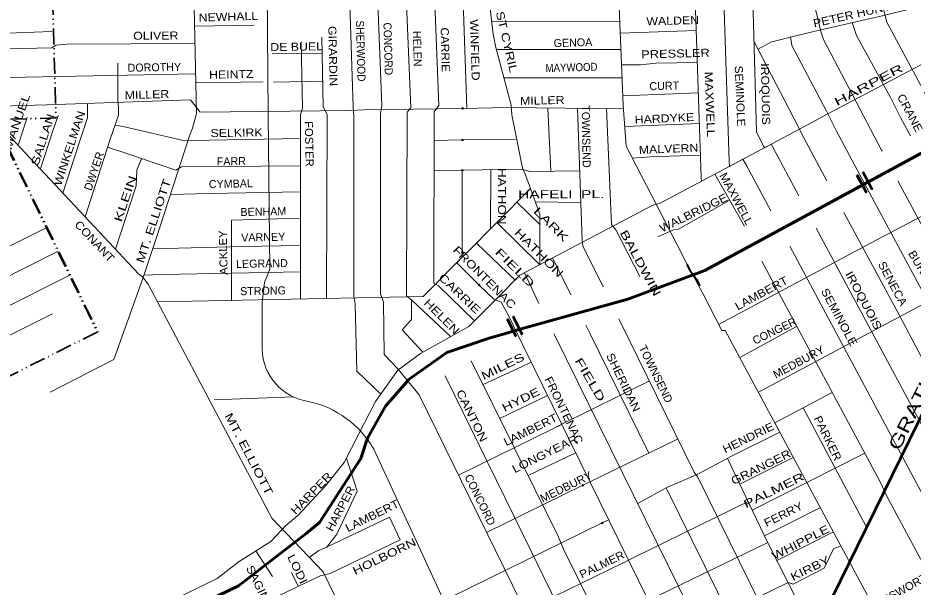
# Model space of a CAD drawing. Extents: x 34705 to 138605, y 34275 to 143551.
# Drawn here: x 100858 to 109243, y 116985 to 122315 of the extents above; entities that cross this region are included whole.
import ezdxf
from ezdxf.enums import TextEntityAlignment as Align

# ---------------------------------------------------------------- set-up
doc = ezdxf.new("R2010")
doc.units = 0
doc.header["$LTSCALE"] = 30
doc.header["$PDMODE"] = 32
doc.header["$PDSIZE"] = 15
doc.linetypes.add('DASH_DOUBLE_DOT', pattern=[9.2, 5, -1.2, 0.3, -1.2, 0.3, -1.2])
for name, color, linetype, lineweight in [('1', 7, 'Continuous', 13), ('11', 7, 'Continuous', 13), ('50', 7, 'Continuous', 13), ('51', 7, 'Continuous', 35), ('59', 7, 'DASH_DOUBLE_DOT', 106)]:
    doc.layers.add(name, color=color, linetype=linetype, lineweight=lineweight)

msp = doc.modelspace()

# ---------------------------------------------------------------- linework, layer by layer
at = {"layer": '1'}
for p, q in [((105027.35, 122464.2), (105063.96, 121468.67)), ((102512.54, 122236.39), (103070.94, 122246.19)), ((105294.72, 122280.67), (106495.17, 122285.71)), ((106499.93, 122172.34), (107210.12, 122197.35)), ((105340.36, 122019.42), (106506.34, 122019.42)), ((103238.5, 121979.98), (103706.88, 121985.02)), ((105409.65, 121754.77), (106517.44, 121754.77)), ((103252.36, 121712.48), (103706.84, 121723.05)), ((106524.58, 121584.56), (107230.94, 121612.16)), ((105014, 121467.85), (105023.8, 121468)), ((105822.22, 121470.77), (105848.2, 120879.51)), ((106541.46, 121299.33), (107241.08, 121327.1)), ((104758.49, 121167.98), (105022.74, 121171.66)), ((105012.19, 121171.48), (105022.74, 121171.63)), ((105022.74, 121171.66), (105519.48, 121178.56)), ((104758.49, 120882.52), (105021.73, 120887.65)), ((105010.45, 120887.4), (105021.73, 120887.62)), ((105018.37, 120887.58), (105019.63, 120301.09)), ((105040.81, 120093.95), (105656.91, 120715.02)), ((105532.32, 120589.42), (105746.37, 120381.6)), ((105704.29, 120592.05), (106130.6, 120586.37)), ((102857.88, 120422.51), (103505.39, 120438.98)), ((102857.88, 120422.51), (102857.88, 119665.83)), ((105019.63, 120300.97), (105020.02, 120120.9)), ((99269.42, 119146.46), (101236.59, 120130.37)), ((105020.02, 120120.9), (105020.02, 120120.24)), ((105036.1, 120089.2), (105040.81, 120093.95)), ((105037.02, 120089.09), (105041.27, 120093.37)), ((105866.33, 120066.75), (106037.13, 119721.74)), ((99381.26, 118924.05), (101345.14, 119906.31)), ((105178.65, 119813.82), (105178.65, 119813.82)), ((105277.58, 119622.72), (105349.19, 119694.35)), ((105277.58, 119622.72), (105349.19, 119694.35)), ((105081.79, 119426.86), (105277.58, 119622.72)), ((107620.36, 119133.63), (108152.17, 119425.93)), ((105414.65, 119357.96), (105506, 119383.57)), ((105574.6, 119048.98), (105652.63, 119085.34)), ((105652.63, 119085.34), (105665.78, 119091.46)), ((105214.89, 118881.39), (105574.6, 119048.98)), ((104859.72, 118963.6), (105661.1, 117328.25)), ((105938.82, 118503.26), (106773.19, 118915.08)), ((105372.16, 118563.86), (105735.52, 118738.13)), ((105735.52, 118738.13), (105806.59, 118772.21)), ((105806.59, 118772.21), (105819.7, 118778.5)), ((108213.12, 118664.44), (108807.71, 117545.53)), ((105873.75, 118471.14), (105938.82, 118503.26)), ((105874.69, 118471.09), (105939.03, 118502.84)), ((104985.66, 118032.79), (105873.75, 118471.14)), ((106203.69, 117964.56), (107035.52, 118371.06)), ((106010.22, 118207.51), (106070.33, 118235.8)), ((106070.33, 118235.8), (106083.54, 118242.02)), ((104037.05, 117884.95), (103936.85, 118193.13)), ((105635.95, 118031.32), (106010.22, 118207.51)), ((107618.46, 117949.89), (108120.95, 118198.39)), ((105248.33, 117497.69), (106149.66, 117938.16)), ((106149.66, 117938.16), (106203.69, 117964.56)), ((106150.62, 117938.12), (106203.89, 117964.15)), ((103846.46, 117479.75), (104037.05, 117884.95)), ((103743.35, 117354.46), (104338.18, 117640.06)), ((104338.18, 117640.06), (104439.72, 117429.24)), ((101946.58, 115440.18), (106331.92, 117586.09)), ((103235.24, 117630.67), (103716.27, 117128.42)), ((106331.92, 117586.09), (106378.55, 117608.91)), ((106331.92, 117586.09), (106378.55, 117608.91)), ((106378.55, 117608.91), (106391.74, 117615.36)), ((103748.97, 117357.16), (103846.46, 117479.75)), ((107965.92, 117235.45), (108496.16, 117503.7)), ((103243.79, 117083.32), (103087.16, 117325.11)), ((103587.67, 117262.7), (103677.32, 117328.13)), ((103677.32, 117328.13), (103743.35, 117354.46)), ((105661.1, 117328.25), (106793.71, 115026.96)), ((105968.83, 117341.08), (107047.11, 115150.16)), ((103420.21, 117122.89), (103484.63, 116992.87))]:
    msp.add_line(p, q, dxfattribs=at)
at = {"layer": '1', "lineweight": 53}
msp.add_lwpolyline([(101368.9, 103017.54), (102548.84, 105055.11), (103212.24, 106184.42), (103282.07, 106324.13), (104294.63, 108304.78), (105138.43, 110039.49), (106145.17, 112117.65), (109289.05, 118526.78), (110743.87, 121478.11), (113275.26, 126686.61), (116465.7, 133274.74), (120395.18, 141348.71), (121157.51, 142914.61), (121243.66, 143093.14)], dxfattribs=at)
at = {"layer": '1'}
for points in [[(105908.84, 142655.73), (106002.49, 139831.85), (106021.72, 138812.17), (106489.73, 122415.45), (106528.19, 121498.37), (106553.84, 121113.59), (107079.54, 120098.72), (107093.68, 120071.85)], [(102374.85, 126669.09), (102396.28, 126261.72), (102409.1, 126024.43), (102377.05, 125960.3), (102396.28, 125543.45), (102409.1, 125408.77), (102428.34, 125254.86), (102460.39, 124049.19), (102460.39, 123978.65), (102498.86, 122702.43), (102505.27, 122561.34), (102530.91, 121416.61), (102492.45, 121281.93), (102466.8, 121211.39), (102152.66, 120249.42), (102030.85, 119883.87), (101755.18, 119117.51), (101158.95, 118809.68)], [(106263.71, 125304.33), (106021.72, 125025.59), (105887.09, 124871.68), (105848.62, 124833.2), (105560.13, 124461.24), (105534.48, 124377.87), (105496.02, 124005.9), (105354.97, 123396.66), (105226.75, 122890.02), (105265.22, 122556.54), (105297.27, 122261.53), (105310.1, 122165.34), (105335.74, 122037.08), (105476.78, 121498.37), (105483.19, 121408.59), (105585.77, 120908.37), (105611.42, 120844.23), (105746.05, 120478.69), (105747.62, 120004.13)], [(108665.24, 124101.95), (108697.65, 123670.07), (108762.34, 123677.67), (108858.01, 122880.22), (108863.83, 122810.42), (108997.57, 122275.29), (109491.61, 121350.64)], [(103922.86, 124068.53), (103960.58, 122635.1), (103999.04, 121480.74), (104005.45, 121390.96), (104005.45, 120416.16), (104005.45, 119710.72), (104018.28, 119633.76), (104031.1, 119008.49), (104256.6, 118790.34)], [(104185.08, 124073.75), (104223.43, 122615.86), (104268.31, 121493.57), (104255.49, 121416.61), (104255.49, 119729.96), (104281.13, 119653), (104289.14, 119164.01), (104417.36, 119029.34), (104616.1, 118785.64), (106525.24, 114896.44)], [(104453.69, 124079.09), (104492.69, 122596.62), (104537.57, 121474.33), (104505.52, 121432.65), (104499.1, 119713.93), (104550.39, 119669.04), (104910.16, 119331.3)], [(104716.92, 124084.33), (104755.55, 122615.86), (104800.42, 121493.57), (104755.55, 121435.85), (104753.94, 119830.97), (104798.82, 119805.32), (105134.66, 119479.75)], [(108143.68, 124059.53), (108154.44, 123898.11), (108173.97, 123608.61), (108238.66, 123616.21), (108340.51, 122740.62), (108392.24, 122480.26), (108311.57, 122461.01), (108381.21, 122176.41), (108404.47, 122112.43), (108945.23, 121077.1), (108951.46, 121065.54)], [(107229.91, 123822.5), (107265.6, 122481.59), (107200.26, 122480.4), (107258.98, 120824.07), (107259.85, 120785.33), (107385.25, 120851.83), (107663.1, 120363.33)], [(107790.96, 122022.99), (107911.74, 122088.44), (108079.3, 122132.81), (108325.71, 122191.96), (108951.6, 122334.93), (109542.99, 122477.9), (109641.56, 122507.48), (110504.01, 122714.53), (111233.39, 122887.08), (111258.03, 122887.08), (111393.51, 122814.8)], [(99925.23, 122819.5), (100622.03, 121373.32), (100698.96, 121296.37), (101987.58, 119917.54), (102026.05, 119891.89), (102077.34, 119821.35), (103235.24, 117630.67)], [(107469.12, 122485.12), (107520.08, 120972.74), (107522.31, 120924.52), (107648.29, 120991.33), (107683.19, 120933.35), (107909.99, 120509.24)], [(107741.03, 122490.04), (107776.48, 121248.68), (107840.45, 121114.9), (107850.71, 121098.69), (107915.86, 121133.24), (107933.48, 121097.45), (108173.94, 120648.83)], [(108672.36, 122271.15), (108712.65, 122150.24), (109032.45, 121568.59), (109125.49, 121382.46), (109218.18, 121209.82)], [(100244.15, 122157.6), (100511.94, 122162.38), (101177.26, 122187.03)], [(103512.33, 122089.75), (103524.63, 121467.91), (103505.39, 121410.2), (103505.39, 119683.21)], [(103703.9, 122134.36), (103716.96, 121480.74), (103755.42, 121410.2), (103749.06, 119687.87)], [(107752.23, 122097.85), (108125.36, 121376.64), (108218.4, 121190.51), (108435.4, 120788.92)], [(108093.55, 122136.23), (108107.92, 122057.18), (108427.73, 121446.44), (108520.76, 121260.31), (108696.71, 120932.51)], [(100315.31, 122009.91), (100462.66, 122019.42), (101177.26, 122034.21), (101216.68, 122058.86), (101315.25, 122068.72), (102516.19, 122073.73)], [(105349.19, 119694.35), (105559.89, 119905.12), (106797.31, 120557.79), (106873.24, 120580.29), (108178.16, 121272.35), (108436.9, 121413.01), (109494.34, 121968.63)], [(101793.64, 121891.18), (101793.64, 121532.04), (101800.06, 121480.74), (101800.06, 121403.78), (101723.12, 121179.32), (101487.65, 120452.47)], [(106512.34, 121876.45), (106689.52, 121876.45), (106832.44, 121891.24), (107220.83, 121896.29)], [(100438.28, 121760.06), (100607.39, 121754.77), (102515.15, 121791.78)], [(102524.41, 121706.9), (103154.6, 121717.77), (103154.6, 121717.77)], [(100580.97, 121485.17), (101125.29, 121501.03), (101130.57, 121501.03), (102475.51, 121548.6), (102565.35, 121432.3), (103971.07, 121448.16), (104097.9, 121453.45), (105023.8, 121468.03)], [(101511.56, 121506.39), (101511.56, 121455.09), (101511.56, 121378.13), (101434.63, 121153.67), (101279.58, 120675.1)], [(105023.8, 121468.03), (105440.21, 121474.59), (106530.51, 121463.69)], [(106098.3, 121468.01), (106143.53, 120233.39), (106149.94, 120182.09), (106338.85, 119798.05)], [(106369.7, 121465.3), (106419.21, 120380.9), (106457.67, 120329.59), (106682.06, 119893.5)], [(100944.91, 121383.2), (100940.98, 121371.72), (100860.55, 121123.47)], [(101233.88, 121400.07), (101184.6, 121256.28), (101069.23, 120900.18)], [(101772.65, 121310.72), (101857.21, 121294.86), (102422.67, 121162.7), (102480.8, 121167.98), (103505.39, 121184.17)], [(101698.67, 121104.55), (101878.35, 121046.4), (102338.11, 120887.81), (102390.96, 120919.52), (103505.39, 120930.35)], [(102016.19, 120996.7), (101973.15, 120890.73), (101966.74, 120743.23), (101770.99, 120149.3)], [(106612.66, 121000.04), (106778.54, 121014.68), (107251.62, 121031)], [(107421.41, 119444.69), (108231.39, 119878.74), (108784.22, 120175.62), (110081.92, 120856.7), (110349.61, 121002.23), (110349.61, 121002.23), (110482.07, 120947.02)], [(108696.71, 120932.51), (109619.74, 119212.88), (109852.32, 118773.74), (110294.24, 117965.24), (110340.75, 117866.35), (112554.87, 113760.08), (112487.03, 113723.4), (115332.38, 108411.13), (115378.66, 108454.42), (115422.3, 108500.45), (116051.29, 107331.62)], [(105021.73, 120887.65), (105572.33, 120898.38), (105656.88, 120877.23), (106119.74, 120882.74)], [(105287.56, 120892.83), (105284.83, 120339.93), (105342.48, 120398.05), (105745.73, 120003.14)], [(109100.82, 120788.27), (110073.28, 118983.13), (110134.33, 118876.98), (112785.82, 113935.83), (112832.34, 113877.67), (113605.69, 112417.71), (113640.58, 112347.91), (114095.57, 111482.7), (114473.52, 110790.53), (114816.59, 110141.99), (114845.66, 110101.28), (115591.68, 108679.26)], [(102290.55, 120660.49), (102649.91, 120671.06), (103505.39, 120687.31)], [(106852.75, 120264.49), (106997.71, 120331.81), (107044.3, 120336.99), (107518.47, 120605.78)], [(108594.76, 120494.01), (109090.6, 119576.42), (109317.37, 119143.08), (110032.58, 117825.64), (110073.28, 117744.21), (110527.06, 116886.14)], [(99156.13, 119371.75), (99320.5, 119451.47), (101128.63, 120353.22)], [(108335.91, 120346.63), (109765.1, 117680.22), (109811.62, 117598.79), (110250.62, 116775.76), (110680.91, 115973.07), (112028.99, 113475.73), (112104.34, 113516.47), (114998.27, 108098.61)], [(102120.43, 120152.71), (102961.7, 120174.14), (103505.39, 120185.03)], [(105153.03, 120207.06), (105514.54, 119859.76), (105559.89, 119905.12), (105602.47, 119927.58), (105737.26, 119641.4)], [(108087.07, 120178.1), (110041.33, 116523.61), (111759.47, 113330.67), (111699.72, 113298.51), (114653.95, 107796.92)], [(102163.46, 119658.41), (102491.29, 119663.79), (104655.2, 119705.22), (105036.1, 120089.2)], [(105020.02, 120120.24), (105020.13, 120073.1), (104967.88, 120020.43), (105178.65, 119813.82)], [(107093.68, 120071.85), (107271.88, 119733.17), (107451.38, 119386.86), (107483.44, 119386.86), (108611.78, 117283.36), (109600.68, 115452.42), (109632.74, 115381.87), (112625.09, 109812.1), (112669.97, 109715.9), (112990.52, 109138.72), (113028.98, 109061.76), (114009.65, 107228.03)], [(107824.55, 120035.9), (108933.6, 117971.05), (109003.38, 117825.64), (110151.77, 115688.06), (113174.43, 110060.91)], [(102038.35, 119906.37), (102211.75, 119912.36), (103505.39, 119938.56)], [(105178.65, 119813.82), (105314.91, 119680.26), (105369.97, 119660.23)], [(107793.19, 118809.42), (109377.79, 119657.54), (109635.64, 119795.51)], [(104545.58, 119673.56), (104545.58, 119489.48), (104455.83, 119393.28), (104652.23, 119185.89)], [(105369.97, 119660.23), (105385.43, 119654.61), (105452.74, 119529.55), (105452.79, 119529.44)], [(98514.34, 118193.55), (99469.67, 118662.1), (99525.32, 118717.77), (101180.93, 119543.52)], [(105452.74, 119529.55), (105596.99, 119231.34), (107558.77, 115242.39), (107610.06, 114960.22), (109071.78, 111984.52), (109078.19, 111881.91), (112490.46, 104910.87), (112500.77, 104893)], [(106487.07, 119496.74), (107193.34, 118060.95), (107225.4, 118016.06), (109967.72, 112447.88), (110019.01, 112409.4), (111921.48, 108574.36), (112510.11, 107358.72)], [(102725.35, 117066.76), (102922.44, 117218.41), (103226.35, 117413.36), (103367.14, 117562.16), (103480.84, 117655.68), (103738.57, 117933.71), (103915.44, 118151.08), (104051.89, 118419.01), (104208.54, 118722.32), (104415.74, 119015.51), (104627.98, 119172.22), (104952.28, 119355.05), (105081.79, 119426.86)], [(106176.99, 119439.25), (106212.45, 119367.63), (106766.6, 118239.64)], [(105878.29, 119360.93), (105888.69, 119340.37), (107789.36, 115482.34)], [(105104.84, 119103.55), (105911.13, 117475.75), (105968.83, 117341.08)], [(106663.36, 117767.93), (106936.59, 117917.01), (107221.74, 118039.25), (107535.98, 118208.07), (107993.08, 118436.76), (107946.5, 118523.6), (108484.18, 118807.8)], [(106564.67, 117230.38), (106633.99, 117265.04), (107697.39, 117785.56), (107736.08, 117705), (108789.3, 118239.72)], [(107502.96, 118190.33), (107879.32, 117406.82), (108174.23, 116823.22), (108719.17, 115707.34), (108764.05, 115598.31), (109632.03, 113841.19)], [(106930.17, 117914.26), (109698.45, 112306.79), (109762.56, 112281.14), (111357.31, 109081), (111966.36, 107830.44), (112261.27, 107227.61), (112786.97, 106156.61)], [(106749.55, 116854.35), (106762.01, 116860.46), (107881.43, 117402.65), (107850.93, 117465.93), (108368.14, 117727.82)], [(102588.74, 116563.5), (103688.16, 117090.41), (103782.53, 117113.69), (104439.72, 117429.24)], [(106937.02, 116473.06), (108071.35, 117029.28), (108117.91, 117011.81), (108408.87, 117163.16), (108496.16, 117343.62), (108565.21, 117370.18)], [(106526.05, 117211.1), (106529.24, 117212.65), (106564.67, 117230.38)], [(106527.03, 117211.06), (106530.26, 117212.64), (106564.88, 117229.95)], [(99706.11, 113869.83), (101213.31, 114609.12), (101993.1, 114993.32), (103092.94, 115534.69), (104221.89, 116087.7), (106526.05, 117211.1)], [(100981.9, 116212.44), (101185.44, 116312.18), (102725.35, 117066.76)], [(103716.27, 117128.42), (103999.04, 116550.67), (104063.15, 116409.58), (104582.45, 115338.59), (105127.85, 114217.1)]]:
    msp.add_lwpolyline(points, dxfattribs=at)
for p in [(105023.8, 121468.03), (105022.74, 121171.66), (105021.73, 120887.65), (105020.02, 120120.24), (105178.65, 119813.82), (106149.66, 117938.16), (106331.92, 117586.09)]:
    msp.add_point(p, dxfattribs=at)
at = {"layer": '50'}
for p, q in [((102694.92, 118739.14), (103438.87, 118765.71)), ((104191.16, 118276.66), (105422.93, 115620.86))]:
    msp.add_line(p, q, dxfattribs=at)
msp.add_lwpolyline([(103215.91, 126697.17), (103166.33, 124020.03), (103193.08, 122576.47), (103203.12, 121405.6), (103218.83, 119961.94), (103168.43, 119836.79), (103144.87, 119648.74), (103145.26, 119214.33)], dxfattribs=at)
for centre, radius, start, end in [((103651.46, 119225.23), 506.32, 181.23458, 262.05404), ((103383.12, 117814.07), 931.08, 29.79037, 77.69999)]:
    msp.add_arc(centre, radius, start, end, dxfattribs=at)
at = {"layer": '51', "lineweight": 60}
for p, q in [((105414.65, 119357.96), (105506, 119383.57)), ((105415.43, 119358.18), (105506, 119383.57)), ((105415.56, 119357.92), (105415.67, 119357.95)), ((105415.67, 119357.95), (105506.13, 119383.31))]:
    msp.add_line(p, q, dxfattribs=at)
for points in [[(105506, 119383.57), (106569.88, 119681.82), (107292.97, 119950.63), (110456.13, 121661.99)], [(89988.97, 108477.92), (90798.22, 108939.62), (92566.47, 110548.39), (93464.95, 111299.42), (94105.99, 111757.01), (95119.35, 112339.78), (95250.63, 112499.83), (96676.31, 113207.77), (97328.93, 113874.92), (97846.67, 114327.24), (98207.01, 114625.98), (98499.02, 114825.57), (98833.46, 115013.44), (99483.55, 115334.66), (102925.69, 116996.78), (103558.52, 117486.18), (103681.6, 117588.78), (104071.36, 118187.96), (104132.9, 118380.85), (104301.11, 118680.44), (104522.65, 118930.79), (104875.48, 119181.13), (105281.64, 119320.67), (105414.65, 119357.96)]]:
    msp.add_lwpolyline(points, dxfattribs=at)
at = {"layer": '51', "lineweight": 40}
for points in [[(108717.23, 120839.52), (108720.58, 120841.31), (108805.62, 120682.04), (108802.27, 120680.25)], [(108772.43, 120869.37), (108775.95, 120871.25), (108860.71, 120712.52), (108857.19, 120710.64)], [(105440.4, 119492.29), (105445.52, 119494.81), (105522.83, 119337.7), (105517.71, 119335.18)], [(105495.97, 119516.62), (105500.73, 119518.96), (105582.54, 119352.7), (105577.78, 119350.36)]]:
    msp.add_lwpolyline(points, close=True, dxfattribs=at)
msp.add_lwpolyline([(107124.6, 120004.94), (107155.58, 119946.97), (107195.63, 119893.45), (107214.36, 119864.88), (107244.99, 119807.4)], dxfattribs=at)
at = {"layer": '59', "lineweight": 35}
for p, q in [((101064.03, 126630.31), (101215.3, 121377.77)), ((100638.66, 121362.71), (101609.92, 119372.21))]:
    msp.add_line(p, q, dxfattribs=at)
msp.add_lwpolyline([(91983.3, 125629.39), (97196.01, 128218.97), (98041.3, 126530.08), (101064.01, 126630.97), (101215.3, 121377.77), (100630.88, 121363.11), (101602.13, 119372.61), (97881.18, 117512.12), (95736.43, 121807.31), (94620.91, 121239.02)], close=True, dxfattribs=at)
msp.add_lwpolyline([(101215.3, 121377.77), (100630.88, 121363.11), (101602.13, 119372.61), (97881.18, 117512.12)], dxfattribs=at)

# ---------------------------------------------------------------- texts
at = {"layer": '11'}
for s, height, rotation, width, p in [('PETER HUNT', 75, 12.867, 1.15, (108675.95, 122307.45)), ('NEWHALL ', 75, 1.8, 1.15, (102846.85, 122289.01)), ('ST CYRIL', 75, 283.082, 1.3, (105400.36, 122082.37)), ('WALDEN ', 75, 1.492, 1.15, (107008.3, 122251.95)), ('SHERWOOD', 75, 271.588, 0.95, (104032.18, 122004.12)), ('CONCORD', 75, 271.588, 0.95, (104288.5, 122024.47)), ('WINFIELD', 75, 271.638, 1.2, (105101.31, 122013.4)), ('OLIVER', 75, 0.37, 1.15, (102149.93, 122111.56)), ('GIRARDIN', 75, 271.299, 1.15, (103771.33, 121956.81)), ('CARRIE', 75, 271.589, 1.1, (104823.32, 122016.15)), ('DE BUEL', 75, 0.92, 1.15, (103469.33, 122007.8)), ('PRESSLER ', 75, 1.492, 1.2, (107034.63, 121943.95)), ('HEINTZ', 75, 0.92, 1.15, (102857.42, 121749.07)), ('MAYWOOD', 75, 1.59, 0.9, (106044.41, 121814.04)), ('SEMINOLE', 75, 272.5, 1.1, (107584.1, 121581.7)), ('IROQUOIS', 75, 271.245, 1.15, (107823.14, 121601.2)), ('HARPER', 75, 27.852, 1.7, (108842.5, 121654.97)), ('MAXWELL  ', 75, 272.258, 1.25, (107302.98, 121469.81)), ('MANUEL  ', 75, 71, 1.3, (100897.9, 121365.15)), ('MILLER', 75, 1.73, 1.15, (102067.87, 121559.66)), ('MILLER', 75, 1.587, 1.15, (105770.41, 121504.71)), ('CRANE', 75, 297.853, 1.1, (109180.29, 121407.15)), ('SALLAN ', 75, 71.885, 1.3, (101133.19, 121180.67)), ('WINKELMAN ', 75, 71.742, 1.2, (101381.21, 121098.36)), ('HARDYKE ', 75, 2.739, 1.15, (106931.19, 121337.38)), ('FOSTER', 75, 271.3, 1.05, (103549.56, 121133.74)), ('SELKIRK', 75, 0.949, 1.15, (102906.81, 121202.35)), ('MALVERN ', 75, 2.298, 1.15, (106969.77, 121052.52)), ('KLEIN  ', 75, 71.308, 1.55, (101913.14, 120650.86)), ('HATHON  ', 75, 270.083, 1.25, (105355.1, 120609.43)), ('MAXWELL', 75, 298.315, 1.1, (107554.36, 120602.86)), ('MT. ELLIOTT', 75, 71.638, 1.35, (102163.98, 120402.45)), ('HAFELI  PL. ', 75, 0.082, 1.45, (105967.61, 120626.6)), ('WALBRIDGE', 75, 26, 1.15, (107201.97, 120455.58)), ('LARK ', 75, 315.081, 1.55, (105840.25, 120339.99)), ('CONANT', 75, 313.144, 1.15, (101549.48, 120197.13)), ('ACKLEY', 75, 91.172, 1.05, (102818.55, 120117.6)), ('HATHON  ', 75, 315.083, 1.4, (105739.36, 120060.72)), ('BALDWIN       ', 75, 298.385, 1.5, (106725.72, 119873.27)), ('FRONTENAC ', 75, 315.081, 1.25, (105214.38, 119846.01)), ('FIELD  ', 75, 315.083, 1.65, (105519.51, 119917.83)), ('BURNS', 75, 300.852, 1.1, (109292.24, 119943.01)), ('SENECA', 75, 298.244, 1.1, (109018.43, 119809.05)), ('CARRIE', 75, 316.59, 1.3, (104970.86, 119705.42)), ('IROQUOIS', 75, 298.178, 1.2, (108745.83, 119652.45)), ('LAMBERT', 75, 28.431, 1.15, (107839.35, 119703.89)), ('SEMINOLE', 75, 298.229, 1.15, (108517.35, 119495.7)), ('HELEN', 75, 315.083, 1.25, (104801.65, 119491.23)), ('MEDBURY', 75, 28.326, 1.05, (108188.23, 119060.57)), ('MILES ', 75, 26.243, 1.45, (105433.87, 119027.45)), ('SHERIDAN', 75, 295.998, 1.15, (106495.93, 118885.93)), ('GRATIOT', 120, 63.557, 1.4, (109334.19, 118700.71)), ('FIELD  ', 75, 300.085, 1.6, (106206.94, 118871.1)), ('FRONTENAC', 75, 295.999, 1.1, (105938.98, 118624.36)), ('CANTON ', 75, 296.107, 1.25, (105084.56, 118557.99)), ('HYDE ', 75, 26.243, 1.35, (105601.72, 118715.44)), ('MT. ELLIOTT', 75, 297.484, 1.4, (102988.68, 118213.93)), ('LAMBERT', 75, 26.243, 1.15, (105675.42, 118424.74)), ('PARKER', 75, 295.998, 1.1, (108410.18, 118362.14)), ('HENDRIE', 75, 26.201, 1.15, (107715.8, 118350.04)), ('LONGYEAR ', 75, 26.242, 1.2, (105825.72, 118205.71)), ('GRANGER ', 75, 26.3, 1.2, (107848.5, 118082.56)), ('HARPER', 75, 45.551, 1.2, (103633.47, 117837.86)), ('MEDBURY', 75, 26.061, 1.05, (106008.78, 117890.9)), ('PALMER     ', 75, 26.199, 1.5, (108048.4, 117904.5)), ('HARPER', 75, 62.553, 1.1, (103911.8, 117703.11)), ('LAMBERT', 75, 26.243, 1.15, (104192.45, 117619.92)), ('FERRY', 75, 26.587, 1.15, (108044.66, 117633.09)), ('WHIPPLE ', 75, 27.01, 1.3, (108220.9, 117378.94)), ('HOLBORN  ', 75, 26.243, 1.3, (104338.67, 117255.01)), ('PALMER', 75, 26.061, 1.1, (106344.6, 117162.97)), ('LODI', 75, 296.064, 1.25, (103442.82, 117138.04)), ('KIRBY', 75, 26.062, 1.3, (108293.29, 117127.21)), ('SAGINAW', 75, 296.064, 1.15, (103112.19, 116920.66)), ('FARNSWORTH', 75, 29.199, 1.05, (109120.85, 116904.44))]:
    msp.add_text(s, height=height, rotation=rotation, dxfattribs=dict(at, width=width)).set_placement(p, align=Align.CENTER)
for s, rotation, p in [('HELEN', 271.587, (104562.19, 122025.25)), ('GENOA', 1.589, (106058.01, 122046.4)), ('DOROTHY', 1.003, (102136.75, 121814.72)), ('CURT', 1.491, (106913.14, 121641.33)), ('TOWNSEND', 270.999, (106143.5, 121203.97)), ('DWYER', 71.409, (101605.86, 120868.26)), ('FARR', 0.951, (102857.84, 120935.26)), ('CYMBAL', 1.173, (102853.54, 120724.77)), ('BENHAM', 1.172, (103157.81, 120463.93)), ('VARNEY', 1.172, (103156.78, 120224.44)), ('LEGRAND', 1.172, (103144.2, 119977.63)), ('STRONG', 1.176, (103154.49, 119722.48)), ('CONGER', 26, (107960.01, 119350.38)), ('TOWNSEND', 295.998, (106799.6, 118964.44)), ('CONCORD', 296.152, (105153.47, 117786.39))]:
    msp.add_text(s, height=75, rotation=rotation, dxfattribs=at).set_placement(p, align=Align.CENTER)

doc.saveas('drawing.dxf')
